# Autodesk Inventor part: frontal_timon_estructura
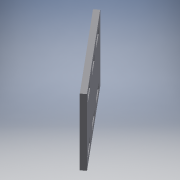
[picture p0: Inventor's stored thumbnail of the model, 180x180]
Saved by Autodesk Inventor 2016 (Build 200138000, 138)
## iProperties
Created: 2017-06
Part Number: frontal_timon_estructura
Material: Generic
Document SubType Name: Modeling
Designer: laboratorioesan
Density: 1 g/cm^3
Appearance: Default
Author: laboratorioesan
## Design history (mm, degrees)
sketch "Sketch1"
  geometry: L1 (-29.189, -4.822)-(-51.614, 22.05) reference; L2 (-47.008, 25.895)-(-22.981, -2.897) reference; L3 (-10.409, -15.199)-(29.692, 18.266) reference; L4 (-43.009, -16.355)-(-65.434, 10.517) reference; L5 (-70.041, 6.673)-(-45.325, -22.944) reference; L6 (-47.008, 25.895)-(-70.041, 6.673) reference; L7 (-31.652, 38.709)-(-432.262, 518.759); L8 (-432.262, 518.759)-(-420.361, 528.69); L9 (-420.361, 528.69)-(-19.752, 48.64); L10 (-31.652, 38.709)-(-19.752, 48.64); L11 (-1131.104, 152.556)-(-641.104, 152.556) reference; L12 (-220.057, 288.665)-(-231.957, 278.734); 1 further point
  constraints: 18 end point, 2 midpoint, 1 parallel, 1 perpendicular, 12 other
  dimensions: "d0" = 20 distance between parallel lines of L7 L2; "d1" = 15.5 distance of L7.end L8.end
extrude "Extrusion1" new body sketch "Sketch1" stored distance "d2" = 200; taper "d3" = 0 deg
sketch "Sketch2"
  geometry: L1 (200, 0)-(0, 0) reference; L2 (0, -312.624)-(0, 0) reference; L3 (200, -312.624)-(0, -312.624) reference; L4 (200, 0)-(200, -312.624) reference; L5 (20, -40)-(35.5, -40); L6 (35.5, -40)-(35.5, -90); L7 (35.5, -90)-(20, -90); L8 (20, -90)-(20, -40); L9 (20, -140)-(35.5, -140); L10 (35.5, -140)-(35.5, -190); L11 (35.5, -190)-(20, -190); L12 (20, -190)-(20, -140); L13 (20, -240)-(35.5, -240); L14 (35.5, -240)-(35.5, -290); L15 (35.5, -290)-(20, -290); L16 (20, -290)-(20, -240); L17 (164.5, -40)-(180, -40); L18 (180, -40)-(180, -90); L19 (180, -90)-(164.5, -90); L20 (164.5, -90)-(164.5, -40); L21 (164.5, -140)-(180, -140); L22 (180, -140)-(180, -190); L23 (180, -190)-(164.5, -190); L24 (164.5, -190)-(164.5, -140); L25 (164.5, -240)-(180, -240); L26 (180, -240)-(180, -290); L27 (180, -290)-(164.5, -290); L28 (164.5, -290)-(164.5, -240); 1 further point
  constraints: 48 end point, 12 parallel, 6 horizontal, 6 horizontal alignment, 6 perpendicular, 5 vertical alignment, 4 point on line
  dimensions: "d4" = 15.5 distance of L6.end L7.end; "d5" = 50 distance of L5.end L6.end; "d6" = 20 horizontal distance of L1.end L5.start; "d7" = 40 vertical distance of L1.end L5.start; "d8" = 50 distance of L9.end L10.end; "d9" = 50 distance between parallel lines of L9 L7; "d10" = 50 distance of L13.end L14.end; "d11" = 50 distance between parallel lines of L13 L11; "d12" = 15.5 distance of L18.end L19.end; "d13" = 20 horizontal distance of L1.start L17.end
extrude "Extrusion2" cut sketch "Sketch2" distance "d14" = 15.5; taper "d15" = 0 deg
body "Solid1"
node "Reference1"
node "Reference2"
node "Reference3"
node "Projected Loop1"
